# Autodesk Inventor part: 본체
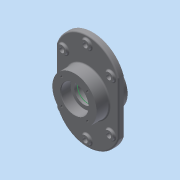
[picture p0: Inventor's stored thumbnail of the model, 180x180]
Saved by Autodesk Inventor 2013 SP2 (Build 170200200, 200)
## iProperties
Created: 2015-02
Part Number: 본체
Material: 일반
Document SubType Name: Modeling
Designer: dgall
Density: 1 g/cm^3
Author: dgall
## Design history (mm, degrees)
sketch "스케치1"
  geometry: L1 (-35, 0)-(35, 0); L2 (-35, 50)-(35, 50); L3 (-35, 31)-(-35, 0); L4 (-35, 50)-(-35, 0); L5 (-35, 50)-(-35, 31); L6 (35, 50)-(35, 0); L7 (-13, 22.5)-(13, 22.5); L8 (-35, 31)-(-13, 31); L9 (13, 31)-(35, 31); L10 (-13, 31)-(-13, 0); L11 (13, 31)-(13, 0); L12 (13, 21.815)-(13, 0); L13 (-13, 22.5)-(-13, 0); L14 (-13, 31)-(-13, 22.5); L15 (13, 31)-(13, 22.5); 2 further points
  constraints: 30 end point, 6 perpendicular, 5 point on line, 4 collinear, 2 coincident, 2 parallel, 2 vertical alignment, 1 horizontal, 1 midpoint
  dimensions: "d0" = 70 distance of L1.start L1.end; "d1" = 100 diameter of L2 L1; "d6" = 45 diameter of L7 L1; "d7" = 62 diameter of L9 L1; "d8" = 62 diameter of L8 L1; "d9" = 22 distance of L9.start L9.end; "d10" = 22 distance of L8.start L8.end
revolve "회전1" sketch "스케치1" stored, may be unused: angle "d11" = 90 deg
sketch "스케치3"
  geometry: L1 (110, 70)-(-110, 70); L2 (-110, 70)-(-110, -70); L3 (-110, -70)-(110, -70); L4 (110, -70)-(110, 70); L5 (60, 70)-(60, -70); A1 r 74 centre (36, 0) between (60, -70) and (60, 70); A2 r 74 centre (-36, 0) between (-60, 70) and (-60, -70); 5 further points
  constraints: 10 end point, 6 point on circle, 4 point on line, 3 midpoint, 2 centre point, 2 coincident, 2 parallel, 2 perpendicular, 2 vertical alignment, 1 horizontal, 1 horizontal alignment
  dimensions: "d12" = 220 distance of L2.end L3.end; "d15" = 140 distance of L1.end L2.end; "d60" = 50 distance between parallel lines of L4 L5; "d64" = 50 distance from line of L2 A2.end
sketch "스케치5"
  geometry: L1 (-28.991, 28.991)-(0, 0); L2 (0, 0)-(-41, 0); C1 r 50 at (0, 0) reference; A1 r 41 centre (0, 0) between (-28.991, 28.991) and (-41, 0); 1 further point
  constraints: 4 end point, 2 coincident, 2 point on circle, 1 centre point, 1 horizontal
  dimensions: "d35" = 82 diameter of A1; "d37" = 45 deg angle of L2 L1
hole "구멍1" sketch "스케치5" at (-28.991, 28.991) diameter "d39" = 4.917; stored, may be unused: countersink angle "d43" = 90 deg, drill point angle "d45" = 118 deg; dims "d40" = 10, "d41" = 4, "d42" = 2, "d44" = 13
fillet "모깎기3" dims "d49" = 0.3
chamfer "모따기1" distance "d54" = 1; stored, may be unused: second distance "d55" = 2, angle "d56" = 45 deg
extrude "돌출6" join sketch "스케치3" stored distance "d65" = 12; taper "d66" = 0 deg
sketch "스케치8"
  geometry: L1 (-70, 60)-(-70, -60) reference; L2 (70, -60)-(70, 60) reference; L3 (53, 56.976)-(53, -56.976); L4 (-53, -56.976)-(-53, 56.976); C1 r 10 at (0, 93); C2 r 10 at (0, -93); C3 r 10 at (53, -56.976); C4 r 10 at (53, 56.976); C5 r 10 at (-53, 56.976); C6 r 10 at (-53, -56.976); C7 r 5.5 at (0, 93); C8 r 5.5 at (53, 56.976); C9 r 5.5 at (-53, 56.976); C10 r 5.5 at (53, -56.976); C11 r 5.5 at (0, -93); C12 r 5.5 at (-53, -56.976); A1 r 74 centre (0, 36) between (70, 60) and (-70, 60) reference; A2 r 74 centre (0, -36) between (-70, -60) and (70, -60) reference; A3 r 57 centre (0, 36) between (53, 56.976) and (-53, 56.976); A4 r 57 centre (0, -36) between (-53, -56.976) and (53, -56.976)
  constraints: 14 centre point, 7 point on circle, 4 end point, 3 coincident, 1 horizontal alignment, 3 other
  dimensions: "d67" = 17 distance between parallel lines of L2 L3; "d68" = 20 diameter of C1; "d69" = 20 diameter of C4; "d70" = 20 diameter of C5; "d71" = 20 diameter of C6; "d72" = 20 diameter of C2; "d73" = 20 diameter of C3; "d76" = 11 diameter of C9; "d77" = 11 diameter of C8; "d78" = 11 diameter of C7; "d79" = 11 diameter of C10; "d80" = 11 diameter of C11; "d81" = 11 diameter of C12
extrude "돌출7" join sketch "스케치8" distance "d74" = 5; taper "d75" = 0 deg
extrude "돌출8" cut sketch "스케치8" stored distance "d82" = 5; taper "d83" = 0 deg
fillet "모깎기6" dims "d84" = 3
fillet "모깎기7" dims "d85" = 3
fillet "모깎기8" dims "d86" = 3
fillet "모깎기9" dims "d87" = 3
sketch "스케치9"
  geometry: C1 r 22.5 at (0, 0) reference
sketch "스케치10"
  geometry: C1 r 22.5 at (0, 0) reference
extrude "돌출9" cut sketch "스케치10" stored distance "d88" = 5; taper "d89" = 0 deg
node "솔리드1"
pattern_circular "원형 패턴1" dims angle "d47" = 360 deg
mirror "대칭1"
